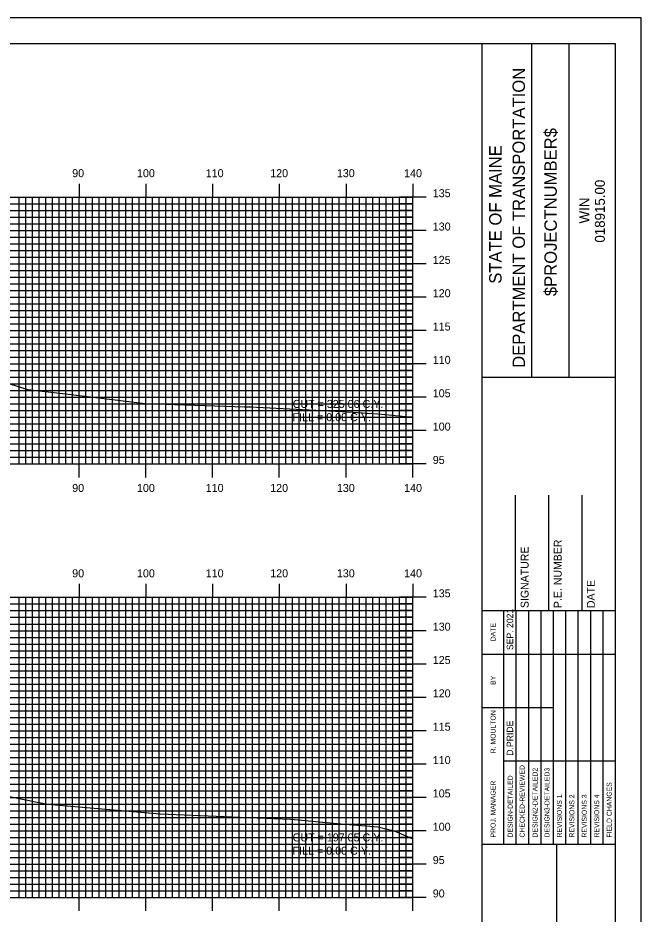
# Model space of a CAD drawing. Extents: x 858052 to 858395, y 364366 to 364586.
# Drawn here: x 858298.2 to 858391.6, y 364451.3 to 364585.7 of the extents above; entities that cross this region are included whole.
import ezdxf

# ---------------------------------------------------------------- set-up
doc = ezdxf.new("R2010")
doc.units = 0
for name, color, linetype in [('BORDER', 7, 'Continuous'), ('D_Text_Standard', 7, 'Continuous'), ('H_V ANNOTATION', 7, 'Continuous'), ('MAJOR', 7, 'Continuous'), ('MINOR', 7, 'Continuous'), ('PLOT BOUNDARY', 7, 'Continuous'), ('S_Roadway_Centerline', 7, 'Continuous')]:
    doc.layers.add(name, color=color, linetype=linetype)

msp = doc.modelspace()

# ---------------------------------------------------------------- linework, layer by layer
at = {"layer": 'BORDER'}
for p, q in [((858367.76, 364371.79), (858367.76, 364581.79)), ((858375.22, 364531.78), (858375.22, 364581.78)), ((858380.81, 364531.78), (858380.81, 364581.78)), ((858367.76, 364531.78), (858387.76, 364531.78)), ((858372.76, 364496.79), (858372.76, 364514.09)), ((858377.76, 364496.79), (858377.76, 364514.09)), ((858382.76, 364496.79), (858382.76, 364514.09)), ((858367.76, 364496.79), (858387.76, 364496.79)), ((858367.76, 364461.79), (858387.76, 364461.79)), ((858378.94, 364391.79), (858378.94, 364461.79))]:
    msp.add_line(p, q, dxfattribs=at)
msp.add_lwpolyline([(858067.76, 364371.79), (858387.76, 364371.79), (858387.76, 364581.79), (858067.76, 364581.79)], close=True, dxfattribs=at)
for points in [[(858370.99, 364490.29), (858370.99, 364496.79)], [(858372.86, 364461.8), (858372.86, 364496.79)], [(858374.72, 364496.79), (858374.72, 364461.8)], [(858376.58, 364461.8), (858376.58, 364496.79)], [(858378.45, 364461.8), (858378.45, 364496.79)], [(858380.31, 364461.8), (858380.31, 364496.79)], [(858382.17, 364461.8), (858382.17, 364496.79)], [(858384.04, 364461.8), (858384.04, 364496.79)], [(858385.9, 364461.8), (858385.9, 364496.79)], [(858370.99, 364461.8), (858370.99, 364495.38)], [(858367.76, 364490.29), (858387.76, 364490.29)], [(858367.76, 364482.29), (858370.99, 364482.29)], [(858370.99, 364482.29), (858378.44, 364482.29)], [(858370.99, 364474.29), (858387.76, 364474.29)]]:
    msp.add_lwpolyline(points, dxfattribs=at)
at = {"layer": 'MAJOR'}
for p, q in [((858307.36, 364560.79), (858307.36, 364558.79)), ((858317.36, 364560.79), (858317.36, 364558.79)), ((858327.36, 364560.79), (858327.36, 364558.79)), ((858337.36, 364560.79), (858337.36, 364558.79)), ((858347.36, 364560.79), (858347.36, 364558.79)), ((858357.36, 364560.79), (858357.36, 364558.79)), ((858077.36, 364558.79), (858357.36, 364558.79)), ((858077.36, 364558.79), (858357.36, 364558.79)), ((858307.36, 364518.79), (858307.36, 364558.79)), ((858317.36, 364518.79), (858317.36, 364558.79)), ((858327.36, 364518.79), (858327.36, 364558.79)), ((858337.36, 364518.79), (858337.36, 364558.79)), ((858347.36, 364518.79), (858347.36, 364558.79)), ((858359.37, 364558.79), (858355.36, 364558.79)), ((858357.36, 364518.79), (858357.36, 364558.79)), ((858357.36, 364518.79), (858357.36, 364558.79)), ((858077.36, 364553.79), (858357.36, 364553.79)), ((858359.37, 364553.79), (858355.36, 364553.79)), ((858077.36, 364548.79), (858357.36, 364548.79)), ((858359.37, 364548.79), (858355.36, 364548.79)), ((858077.36, 364543.79), (858357.36, 364543.79)), ((858359.37, 364543.79), (858355.36, 364543.79)), ((858077.36, 364538.79), (858357.36, 364538.79)), ((858359.37, 364538.79), (858355.36, 364538.79)), ((858077.36, 364533.79), (858357.36, 364533.79)), ((858359.37, 364533.79), (858355.36, 364533.79)), ((858077.36, 364528.79), (858357.36, 364528.79)), ((858359.37, 364528.79), (858355.36, 364528.79)), ((858077.36, 364523.79), (858357.36, 364523.79)), ((858359.37, 364523.79), (858355.36, 364523.79)), ((858077.36, 364518.79), (858357.36, 364518.79)), ((858077.36, 364518.79), (858357.36, 364518.79)), ((858307.36, 364516.78), (858307.36, 364518.79)), ((858317.36, 364516.78), (858317.36, 364518.79)), ((858327.36, 364516.78), (858327.36, 364518.79)), ((858337.36, 364516.78), (858337.36, 364518.79)), ((858347.36, 364516.78), (858347.36, 364518.79)), ((858359.37, 364518.79), (858355.36, 364518.79)), ((858357.36, 364516.78), (858357.36, 364518.79)), ((858307.36, 364500.79), (858307.36, 364498.79)), ((858317.36, 364500.79), (858317.36, 364498.79)), ((858327.36, 364500.79), (858327.36, 364498.79)), ((858337.36, 364500.79), (858337.36, 364498.79)), ((858347.36, 364500.79), (858347.36, 364498.79)), ((858357.36, 364500.79), (858357.36, 364498.79)), ((858077.36, 364498.79), (858357.36, 364498.79)), ((858077.36, 364498.79), (858357.36, 364498.79)), ((858307.36, 364453.79), (858307.36, 364498.79)), ((858317.36, 364453.79), (858317.36, 364498.79)), ((858327.36, 364453.79), (858327.36, 364498.79)), ((858337.36, 364453.79), (858337.36, 364498.79)), ((858347.36, 364453.79), (858347.36, 364498.79)), ((858359.37, 364498.79), (858355.36, 364498.79)), ((858357.36, 364453.79), (858357.36, 364498.79)), ((858357.36, 364453.79), (858357.36, 364498.79)), ((858077.36, 364493.79), (858357.36, 364493.79)), ((858359.37, 364493.79), (858355.36, 364493.79)), ((858077.36, 364488.79), (858357.36, 364488.79)), ((858359.37, 364488.79), (858355.36, 364488.79)), ((858077.36, 364483.79), (858357.36, 364483.79)), ((858359.37, 364483.79), (858355.36, 364483.79)), ((858077.36, 364478.79), (858357.36, 364478.79)), ((858359.37, 364478.79), (858355.36, 364478.79)), ((858077.36, 364473.79), (858357.36, 364473.79)), ((858359.37, 364473.79), (858355.36, 364473.79)), ((858077.36, 364468.79), (858357.36, 364468.79)), ((858359.37, 364468.79), (858355.36, 364468.79)), ((858077.36, 364463.79), (858357.36, 364463.79)), ((858359.37, 364463.79), (858355.36, 364463.79)), ((858077.36, 364458.79), (858357.36, 364458.79)), ((858359.37, 364458.79), (858355.36, 364458.79)), ((858077.36, 364453.79), (858357.36, 364453.79)), ((858077.36, 364453.79), (858357.36, 364453.79)), ((858307.36, 364451.78), (858307.36, 364453.79)), ((858317.36, 364451.78), (858317.36, 364453.79)), ((858327.36, 364451.78), (858327.36, 364453.79)), ((858337.36, 364451.78), (858337.36, 364453.79)), ((858347.36, 364451.78), (858347.36, 364453.79)), ((858359.37, 364453.79), (858355.36, 364453.79)), ((858357.36, 364451.78), (858357.36, 364453.79))]:
    msp.add_line(p, q, dxfattribs=at)
at = {"layer": 'MINOR'}
for p, q in [((858298.36, 364518.79), (858298.36, 364558.79)), ((858299.36, 364518.79), (858299.36, 364558.79)), ((858300.36, 364518.79), (858300.36, 364558.79)), ((858301.36, 364518.79), (858301.36, 364558.79)), ((858302.36, 364518.79), (858302.36, 364558.79)), ((858303.36, 364518.79), (858303.36, 364558.79)), ((858304.36, 364518.79), (858304.36, 364558.79)), ((858305.36, 364518.79), (858305.36, 364558.79)), ((858306.36, 364518.79), (858306.36, 364558.79)), ((858308.36, 364518.79), (858308.36, 364558.79)), ((858309.36, 364518.79), (858309.36, 364558.79)), ((858310.36, 364518.79), (858310.36, 364558.79)), ((858311.36, 364518.79), (858311.36, 364558.79)), ((858312.36, 364518.79), (858312.36, 364558.79)), ((858313.36, 364518.79), (858313.36, 364558.79)), ((858314.36, 364518.79), (858314.36, 364558.79)), ((858315.36, 364518.79), (858315.36, 364558.79)), ((858316.36, 364518.79), (858316.36, 364558.79)), ((858318.36, 364518.79), (858318.36, 364558.79)), ((858319.36, 364518.79), (858319.36, 364558.79)), ((858320.36, 364518.79), (858320.36, 364558.79)), ((858321.36, 364518.79), (858321.36, 364558.79)), ((858322.36, 364518.79), (858322.36, 364558.79)), ((858323.36, 364518.79), (858323.36, 364558.79)), ((858324.36, 364518.79), (858324.36, 364558.79)), ((858325.36, 364518.79), (858325.36, 364558.79)), ((858326.36, 364518.79), (858326.36, 364558.79)), ((858328.36, 364518.79), (858328.36, 364558.79)), ((858329.36, 364518.79), (858329.36, 364558.79)), ((858330.36, 364518.79), (858330.36, 364558.79)), ((858331.36, 364518.79), (858331.36, 364558.79)), ((858332.36, 364518.79), (858332.36, 364558.79)), ((858333.36, 364518.79), (858333.36, 364558.79)), ((858334.36, 364518.79), (858334.36, 364558.79)), ((858335.36, 364518.79), (858335.36, 364558.79)), ((858336.36, 364518.79), (858336.36, 364558.79)), ((858338.36, 364518.79), (858338.36, 364558.79)), ((858339.36, 364518.79), (858339.36, 364558.79)), ((858340.36, 364518.79), (858340.36, 364558.79)), ((858341.36, 364518.79), (858341.36, 364558.79)), ((858342.36, 364518.79), (858342.36, 364558.79)), ((858343.36, 364518.79), (858343.36, 364558.79)), ((858344.36, 364518.79), (858344.36, 364558.79)), ((858345.36, 364518.79), (858345.36, 364558.79)), ((858346.36, 364518.79), (858346.36, 364558.79)), ((858348.36, 364518.79), (858348.36, 364558.79)), ((858349.36, 364518.79), (858349.36, 364558.79)), ((858350.36, 364518.79), (858350.36, 364558.79)), ((858351.36, 364518.79), (858351.36, 364558.79)), ((858352.36, 364518.79), (858352.36, 364558.79)), ((858353.36, 364518.79), (858353.36, 364558.79)), ((858354.36, 364518.79), (858354.36, 364558.79)), ((858355.36, 364518.79), (858355.36, 364558.79)), ((858356.36, 364518.79), (858356.36, 364558.79)), ((858077.36, 364557.79), (858357.36, 364557.79)), ((858357.36, 364557.79), (858355.36, 364557.79)), ((858077.36, 364556.79), (858357.36, 364556.79)), ((858357.36, 364556.79), (858355.36, 364556.79)), ((858077.36, 364555.79), (858357.36, 364555.79)), ((858077.36, 364554.79), (858357.36, 364554.79)), ((858357.36, 364555.79), (858355.36, 364555.79)), ((858357.36, 364554.79), (858355.36, 364554.79)), ((858077.36, 364552.79), (858357.36, 364552.79)), ((858357.36, 364552.79), (858355.36, 364552.79)), ((858077.36, 364551.79), (858357.36, 364551.79)), ((858077.36, 364550.79), (858357.36, 364550.79)), ((858357.36, 364551.79), (858355.36, 364551.79)), ((858357.36, 364550.79), (858355.36, 364550.79)), ((858077.36, 364549.79), (858357.36, 364549.79)), ((858357.36, 364549.79), (858355.36, 364549.79)), ((858077.36, 364547.79), (858357.36, 364547.79)), ((858077.36, 364546.79), (858357.36, 364546.79)), ((858357.36, 364547.79), (858355.36, 364547.79)), ((858357.36, 364546.79), (858355.36, 364546.79)), ((858077.36, 364545.79), (858357.36, 364545.79)), ((858357.36, 364545.79), (858355.36, 364545.79)), ((858077.36, 364544.79), (858357.36, 364544.79)), ((858357.36, 364544.79), (858355.36, 364544.79)), ((858077.36, 364542.79), (858357.36, 364542.79)), ((858357.36, 364542.79), (858355.36, 364542.79)), ((858077.36, 364541.79), (858357.36, 364541.79)), ((858357.36, 364541.79), (858355.36, 364541.79)), ((858077.36, 364540.79), (858357.36, 364540.79)), ((858357.36, 364540.79), (858355.36, 364540.79)), ((858077.36, 364539.79), (858357.36, 364539.79)), ((858357.36, 364539.79), (858355.36, 364539.79)), ((858077.36, 364537.79), (858357.36, 364537.79)), ((858357.36, 364537.79), (858355.36, 364537.79)), ((858077.36, 364536.79), (858357.36, 364536.79)), ((858357.36, 364536.79), (858355.36, 364536.79)), ((858077.36, 364535.79), (858357.36, 364535.79)), ((858077.36, 364534.79), (858357.36, 364534.79)), ((858357.36, 364535.79), (858355.36, 364535.79)), ((858357.36, 364534.79), (858355.36, 364534.79)), ((858077.36, 364532.79), (858357.36, 364532.79)), ((858357.36, 364532.79), (858355.36, 364532.79)), ((858077.36, 364531.79), (858357.36, 364531.79)), ((858077.36, 364530.79), (858357.36, 364530.79)), ((858357.36, 364531.79), (858355.36, 364531.79)), ((858357.36, 364530.79), (858355.36, 364530.79)), ((858077.36, 364529.79), (858357.36, 364529.79)), ((858357.36, 364529.79), (858355.36, 364529.79)), ((858077.36, 364527.79), (858357.36, 364527.79)), ((858077.36, 364526.79), (858357.36, 364526.79)), ((858357.36, 364527.79), (858355.36, 364527.79)), ((858357.36, 364526.79), (858355.36, 364526.79)), ((858077.36, 364525.79), (858357.36, 364525.79)), ((858357.36, 364525.79), (858355.36, 364525.79)), ((858077.36, 364524.79), (858357.36, 364524.79)), ((858357.36, 364524.79), (858355.36, 364524.79)), ((858077.36, 364522.79), (858357.36, 364522.79)), ((858357.36, 364522.79), (858355.36, 364522.79)), ((858077.36, 364521.79), (858357.36, 364521.79)), ((858357.36, 364521.79), (858355.36, 364521.79)), ((858077.36, 364520.79), (858357.36, 364520.79)), ((858357.36, 364520.79), (858355.36, 364520.79)), ((858077.36, 364519.79), (858357.36, 364519.79)), ((858357.36, 364519.79), (858355.36, 364519.79)), ((858298.36, 364453.79), (858298.36, 364498.79)), ((858299.36, 364453.79), (858299.36, 364498.79)), ((858300.36, 364453.79), (858300.36, 364498.79)), ((858301.36, 364453.79), (858301.36, 364498.79)), ((858302.36, 364453.79), (858302.36, 364498.79)), ((858303.36, 364453.79), (858303.36, 364498.79)), ((858304.36, 364453.79), (858304.36, 364498.79)), ((858305.36, 364453.79), (858305.36, 364498.79)), ((858306.36, 364453.79), (858306.36, 364498.79)), ((858308.36, 364453.79), (858308.36, 364498.79)), ((858309.36, 364453.79), (858309.36, 364498.79)), ((858310.36, 364453.79), (858310.36, 364498.79)), ((858311.36, 364453.79), (858311.36, 364498.79)), ((858312.36, 364453.79), (858312.36, 364498.79)), ((858313.36, 364453.79), (858313.36, 364498.79)), ((858314.36, 364453.79), (858314.36, 364498.79)), ((858315.36, 364453.79), (858315.36, 364498.79)), ((858316.36, 364453.79), (858316.36, 364498.79)), ((858318.36, 364453.79), (858318.36, 364498.79)), ((858319.36, 364453.79), (858319.36, 364498.79)), ((858320.36, 364453.79), (858320.36, 364498.79)), ((858321.36, 364453.79), (858321.36, 364498.79)), ((858322.36, 364453.79), (858322.36, 364498.79)), ((858323.36, 364453.79), (858323.36, 364498.79)), ((858324.36, 364453.79), (858324.36, 364498.79)), ((858325.36, 364453.79), (858325.36, 364498.79)), ((858326.36, 364453.79), (858326.36, 364498.79)), ((858328.36, 364453.79), (858328.36, 364498.79)), ((858329.36, 364453.79), (858329.36, 364498.79)), ((858330.36, 364453.79), (858330.36, 364498.79)), ((858331.36, 364453.79), (858331.36, 364498.79)), ((858332.36, 364453.79), (858332.36, 364498.79)), ((858333.36, 364453.79), (858333.36, 364498.79)), ((858334.36, 364453.79), (858334.36, 364498.79)), ((858335.36, 364453.79), (858335.36, 364498.79)), ((858336.36, 364453.79), (858336.36, 364498.79)), ((858338.36, 364453.79), (858338.36, 364498.79)), ((858339.36, 364453.79), (858339.36, 364498.79)), ((858340.36, 364453.79), (858340.36, 364498.79)), ((858341.36, 364453.79), (858341.36, 364498.79)), ((858342.36, 364453.79), (858342.36, 364498.79)), ((858343.36, 364453.79), (858343.36, 364498.79)), ((858344.36, 364453.79), (858344.36, 364498.79)), ((858345.36, 364453.79), (858345.36, 364498.79)), ((858346.36, 364453.79), (858346.36, 364498.79)), ((858348.36, 364453.79), (858348.36, 364498.79)), ((858349.36, 364453.79), (858349.36, 364498.79)), ((858350.36, 364453.79), (858350.36, 364498.79)), ((858351.36, 364453.79), (858351.36, 364498.79)), ((858352.36, 364453.79), (858352.36, 364498.79)), ((858353.36, 364453.79), (858353.36, 364498.79)), ((858354.36, 364453.79), (858354.36, 364498.79)), ((858355.36, 364453.79), (858355.36, 364498.79)), ((858356.36, 364453.79), (858356.36, 364498.79)), ((858077.36, 364497.79), (858357.36, 364497.79)), ((858357.36, 364497.79), (858355.36, 364497.79)), ((858077.36, 364496.79), (858357.36, 364496.79)), ((858077.36, 364495.79), (858357.36, 364495.79)), ((858357.36, 364496.79), (858355.36, 364496.79)), ((858357.36, 364495.79), (858355.36, 364495.79)), ((858077.36, 364494.79), (858357.36, 364494.79)), ((858357.36, 364494.79), (858355.36, 364494.79)), ((858077.36, 364492.79), (858357.36, 364492.79)), ((858077.36, 364491.79), (858357.36, 364491.79)), ((858357.36, 364492.79), (858355.36, 364492.79)), ((858357.36, 364491.79), (858355.36, 364491.79)), ((858077.36, 364490.79), (858357.36, 364490.79)), ((858357.36, 364490.79), (858355.36, 364490.79)), ((858077.36, 364489.79), (858357.36, 364489.79)), ((858357.36, 364489.79), (858355.36, 364489.79)), ((858077.36, 364487.79), (858357.36, 364487.79)), ((858357.36, 364487.79), (858355.36, 364487.79)), ((858077.36, 364486.79), (858357.36, 364486.79)), ((858357.36, 364486.79), (858355.36, 364486.79)), ((858077.36, 364485.79), (858357.36, 364485.79)), ((858357.36, 364485.79), (858355.36, 364485.79)), ((858077.36, 364484.79), (858357.36, 364484.79)), ((858357.36, 364484.79), (858355.36, 364484.79)), ((858077.36, 364482.79), (858357.36, 364482.79)), ((858357.36, 364482.79), (858355.36, 364482.79)), ((858077.36, 364481.79), (858357.36, 364481.79)), ((858357.36, 364481.79), (858355.36, 364481.79)), ((858077.36, 364480.79), (858357.36, 364480.79)), ((858077.36, 364479.79), (858357.36, 364479.79)), ((858357.36, 364480.79), (858355.36, 364480.79)), ((858357.36, 364479.79), (858355.36, 364479.79)), ((858077.36, 364477.79), (858357.36, 364477.79)), ((858357.36, 364477.79), (858355.36, 364477.79)), ((858077.36, 364476.79), (858357.36, 364476.79)), ((858077.36, 364475.79), (858357.36, 364475.79)), ((858357.36, 364476.79), (858355.36, 364476.79)), ((858357.36, 364475.79), (858355.36, 364475.79)), ((858077.36, 364474.79), (858357.36, 364474.79)), ((858357.36, 364474.79), (858355.36, 364474.79)), ((858077.36, 364472.79), (858357.36, 364472.79)), ((858357.36, 364472.79), (858355.36, 364472.79)), ((858077.36, 364471.79), (858357.36, 364471.79)), ((858357.36, 364471.79), (858355.36, 364471.79)), ((858077.36, 364470.79), (858357.36, 364470.79)), ((858357.36, 364470.79), (858355.36, 364470.79)), ((858077.36, 364469.79), (858357.36, 364469.79)), ((858357.36, 364469.79), (858355.36, 364469.79)), ((858077.36, 364467.79), (858357.36, 364467.79)), ((858357.36, 364467.79), (858355.36, 364467.79)), ((858077.36, 364466.79), (858357.36, 364466.79)), ((858357.36, 364466.79), (858355.36, 364466.79)), ((858077.36, 364465.79), (858357.36, 364465.79)), ((858077.36, 364464.79), (858357.36, 364464.79)), ((858357.36, 364465.79), (858355.36, 364465.79)), ((858357.36, 364464.79), (858355.36, 364464.79)), ((858077.36, 364462.79), (858357.36, 364462.79)), ((858357.36, 364462.79), (858355.36, 364462.79)), ((858077.36, 364461.79), (858357.36, 364461.79)), ((858077.36, 364460.79), (858357.36, 364460.79)), ((858357.36, 364461.79), (858355.36, 364461.79)), ((858357.36, 364460.79), (858355.36, 364460.79)), ((858077.36, 364459.79), (858357.36, 364459.79)), ((858357.36, 364459.79), (858355.36, 364459.79)), ((858077.36, 364457.79), (858357.36, 364457.79)), ((858077.36, 364456.79), (858357.36, 364456.79)), ((858357.36, 364457.79), (858355.36, 364457.79)), ((858357.36, 364456.79), (858355.36, 364456.79)), ((858077.36, 364455.79), (858357.36, 364455.79)), ((858357.36, 364455.79), (858355.36, 364455.79)), ((858077.36, 364454.79), (858357.36, 364454.79)), ((858357.36, 364454.79), (858355.36, 364454.79))]:
    msp.add_line(p, q, dxfattribs=at)
at = {"layer": 'PLOT BOUNDARY'}
msp.add_lwpolyline([(858051.57, 364365.67), (858391.57, 364365.67), (858391.57, 364585.67), (858051.57, 364585.67)], close=True, dxfattribs=at)
at = {"layer": 'S_Roadway_Centerline'}
for points in [[(858291.04, 364532.64), (858299.68, 364529.94), (858306.18, 364529.22), (858317.25, 364527.87), (858332.16, 364527.37), (858333.42, 364527.34), (858333.94, 364527.32), (858346.8, 364526.65), (858352.14, 364526.29), (858357.36, 364525.8)], [(858288.89, 364470.57), (858301.07, 364468.05), (858302.38, 364467.81), (858303.25, 364467.71), (858319.53, 364466.32), (858331.48, 364465.83), (858336.55, 364465.61), (858339.1, 364465.55), (858346.04, 364464.88), (858352.14, 364464.36), (858354.59, 364463.76), (858357.36, 364462.57)]]:
    msp.add_lwpolyline(points, dxfattribs=at)

# ---------------------------------------------------------------- texts
at = {"layer": 'BORDER'}
for s, height, p in [('DEPARTMENT OF TRANSPORTATION', 1.8635, (858374.18, 364533.2)), ('$PROJECTNUMBER$', 1.8635, (858378.95, 364543.95)), ('STATE OF MAINE', 1.8635, (858370.67, 364545.81)), ('018915.00', 1.491, (858386.15, 364551.98)), ('WIN', 1.491, (858383.84, 364554.85)), ('P.E. NUMBER', 1.1811, (858379.68, 364497.18)), ('SIGNATURE', 1.181, (858374.72, 364497.18)), ('DATE', 1.181, (858384.64, 364497.18)), ('SEP. 2021', 0.969, (858372.41, 364490.88)), ('DATE', 0.743, (858369.77, 364492.2)), ('BY', 0.743, (858369.77, 364485.66)), ('R. MOULTON', 0.745, (858369.77, 364475.4)), ('D.PRIDE', 0.969, (858372.41, 364475.04)), ('CHECKED-REVIEWED', 0.7455, (858374.12, 364462.77)), ('DESIGN2-DETAILED2', 0.7455, (858376.06, 364462.77)), ('DESIGN3-DETAILED3', 0.7455, (858377.85, 364462.77)), ('DESIGN-DETAILED', 0.7455, (858372.33, 364462.77)), ('PROJ. MANAGER', 0.7455, (858369.77, 364462.77)), ('FIELD CHANGES', 0.7455, (858387.17, 364462.77)), ('REVISIONS 1', 0.7455, (858379.71, 364462.77)), ('REVISIONS 2', 0.7455, (858381.58, 364462.77)), ('REVISIONS 3', 0.7455, (858383.44, 364462.77)), ('REVISIONS 4', 0.7455, (858385.3, 364462.77))]:
    msp.add_text(s, height=height, rotation=90, dxfattribs=at).set_placement(p)
at = {"layer": 'D_Text_Standard'}
for s, p in [('CUT = 325.06 C.Y.', (858339.36, 364527.19)), ('FILL = 0.00 C.Y.', (858339.36, 364525.2)), ('CUT = 197.05 C.Y.', (858339.36, 364462.19)), ('FILL = 0.00 C.Y.', (858339.36, 364460.2))]:
    msp.add_text(s, height=1.2, dxfattribs=at).set_placement(p)
at = {"layer": 'H_V ANNOTATION'}
for s, p in [('90', (858306.33, 364561.79)), ('100', (858316.04, 364561.79)), ('110', (858326.34, 364561.79)), ('120', (858336, 364561.79)), ('130', (858345.99, 364561.79)), ('140', (858356.07, 364561.79)), ('135', (858360.36, 364558.79)), ('130', (858360.36, 364553.79)), ('125', (858360.36, 364548.79)), ('120', (858360.36, 364543.79)), ('115', (858360.36, 364538.79)), ('110', (858360.36, 364533.79)), ('105', (858360.36, 364528.79)), ('100', (858360.36, 364523.79)), ('95', (858360.36, 364518.79)), ('90', (858306.33, 364514.59)), ('100', (858316.04, 364514.59)), ('110', (858326.34, 364514.59)), ('120', (858336, 364514.59)), ('130', (858345.99, 364514.59)), ('140', (858356.07, 364514.59)), ('90', (858306.33, 364501.79)), ('100', (858316.04, 364501.79)), ('110', (858326.34, 364501.79)), ('120', (858336, 364501.79)), ('130', (858345.99, 364501.79)), ('140', (858356.07, 364501.79)), ('135', (858360.36, 364498.79)), ('130', (858360.36, 364493.79)), ('125', (858360.36, 364488.79)), ('120', (858360.36, 364483.79)), ('115', (858360.36, 364478.79)), ('110', (858360.36, 364473.79)), ('105', (858360.36, 364468.79)), ('100', (858360.36, 364463.79)), ('95', (858360.36, 364458.79)), ('90', (858360.36, 364453.79))]:
    msp.add_text(s, height=1.2, dxfattribs=at).set_placement(p)

doc.saveas('drawing.dxf')
